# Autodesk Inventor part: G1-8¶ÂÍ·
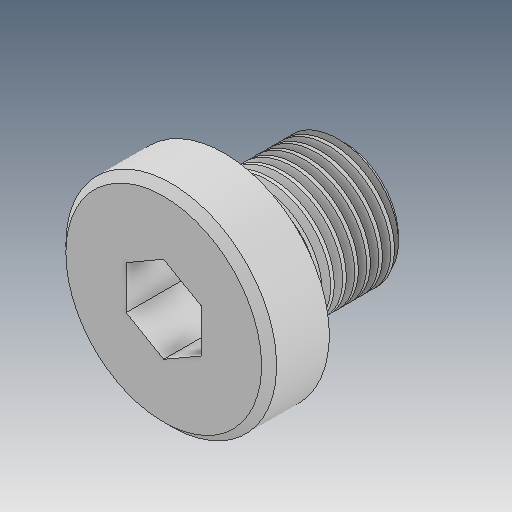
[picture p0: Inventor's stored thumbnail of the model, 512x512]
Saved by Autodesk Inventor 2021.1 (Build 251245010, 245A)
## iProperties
Created: 2019-12
Part Number: G1-8¶ÂÍ·
Material: Ogólny
Document SubType Name: Modeling
Designer: user
Density: 1 g/cm^3
Appearance: Domyślna
Author: user
Revision Number: ÈÎºÎ
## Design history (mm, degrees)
feature "ÊäÈë1"
node "Bryła1"
